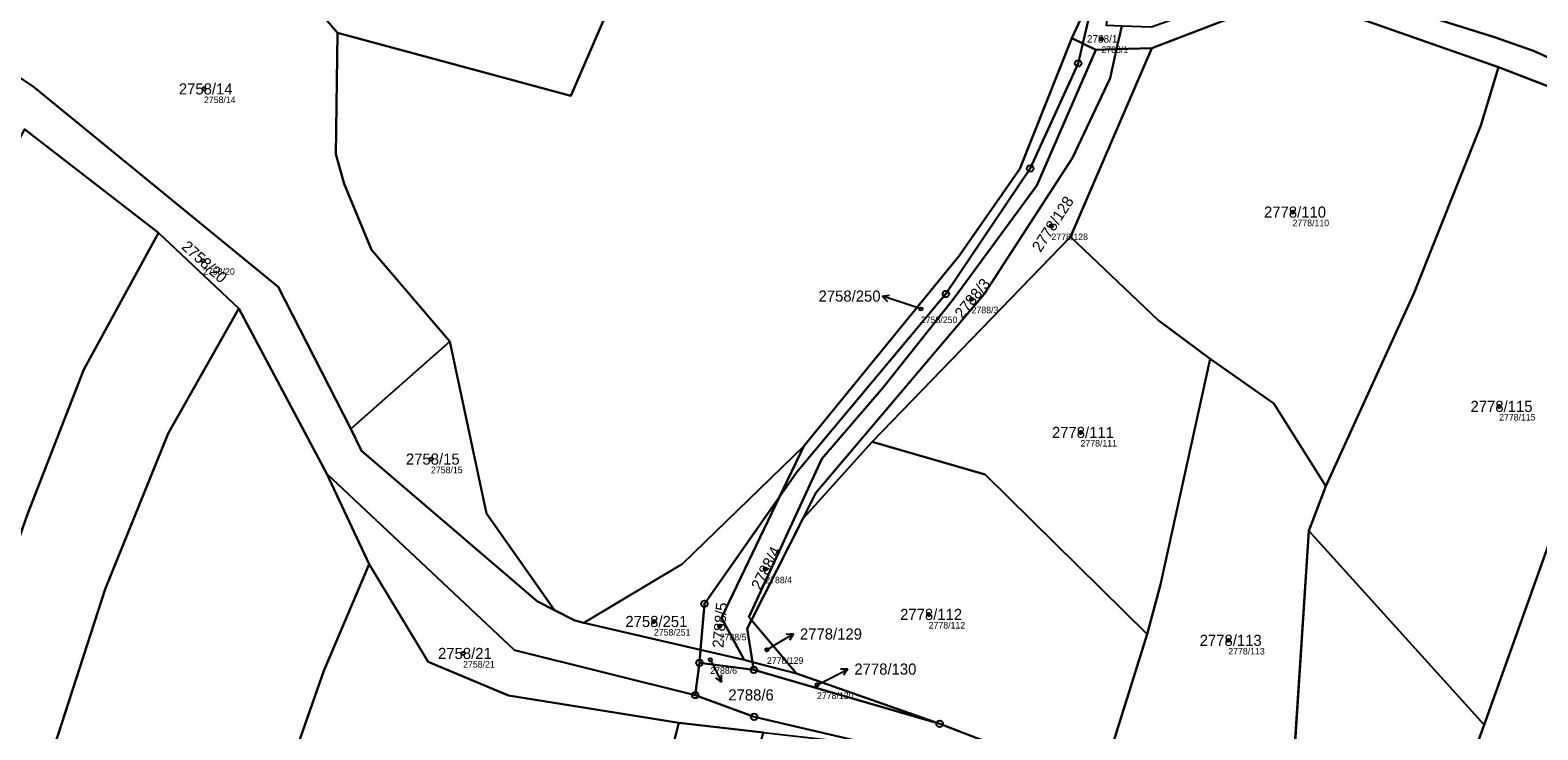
# Model space of a CAD drawing. Extents: x -739214 to -733252, y -1147612 to -1142842.
# Drawn here: x -738174 to -737943.5, y -1144167.5 to -1144060.6 of the extents above; entities that cross this region are included whole.
import ezdxf

# ---------------------------------------------------------------- set-up
doc = ezdxf.new("R2010")
doc.units = 0
for name, color, linetype in [('Definiční body', 7, 'Continuous'), ('Hranice parcel', 7, 'Continuous'), ('Parcelní čísla', 7, 'Continuous'), ('Polygon parcely', 7, 'Continuous'), ('Pop  PČ popisy', 7, 'Continuous'), ('Značky bodu BP', 7, 'Continuous')]:
    doc.layers.add(name, color=color, linetype=linetype)

msp = doc.modelspace()

# ---------------------------------------------------------------- linework, layer by layer
at = {"layer": 'Definiční body'}
for centre in [(-738010.25, -1144061.91), (-738147.45, -1144069.56), (-737981.03, -1144088.39), (-738017.89, -1144090.51), (-738147.58, -1144095.81), (-738037.85, -1144103.2), (-738030.1, -1144101.7), (-737949.46, -1144118.09), (-738013.45, -1144122.07), (-738112.74, -1144126.15), (-738061.64, -1144142.97), (-738078.66, -1144150.97), (-738068.61, -1144151.7), (-738036.66, -1144149.89), (-737990.86, -1144153.86), (-738107.83, -1144155.86), (-738061.39, -1144155.29), (-738070.05, -1144156.82), (-738053.73, -1144160.66)]:
    msp.add_circle(centre, 0.25, dxfattribs=at)
at = {"layer": 'Hranice parcel'}
for p, q in [((-738013.1, -1144062.62), (-738009.89, -1144048.95)), ((-738007.14, -1144059.96), (-738007.93, -1144063.48)), ((-738002.53, -1144063.31), (-738014.98, -1144092.16)), ((-738014.77, -1144061.81), (-738013.1, -1144062.62)), ((-738013.1, -1144062.62), (-738011.1, -1144063.58)), ((-738011.1, -1144063.58), (-738007.93, -1144063.48)), ((-738007.93, -1144063.48), (-738002.53, -1144063.31)), ((-737919.88, -1144077.7), (-737949.57, -1144066.24)), ((-738174.89, -1144075.7), (-738154.42, -1144091.58)), ((-737951.75, -1144166.77), (-737919.88, -1144077.7)), ((-738154.42, -1144091.58), (-738142.14, -1144103.13)), ((-738014.98, -1144092.16), (-738045.31, -1144123.51)), ((-738142.14, -1144103.13), (-738128.69, -1144128.42)), ((-738125, -1144121.52), (-738109.86, -1144108.18)), ((-738045.31, -1144123.51), (-738055.92, -1144135.29)), ((-738055.76, -1144124.16), (-738059.47, -1144131.9)), ((-738128.69, -1144128.42), (-738122.19, -1144142.23)), ((-737978.57, -1144137.13), (-737975.97, -1144130.27)), ((-738055.92, -1144135.29), (-738063.75, -1144150.77)), ((-737981.88, -1144188.4), (-737978.57, -1144137.13)), ((-737951.75, -1144166.77), (-737978.57, -1144137.13)), ((-738071.52, -1144155.32), (-738089.39, -1144151.16)), ((-738063.75, -1144150.77), (-738056.85, -1144158.93)), ((-738010.51, -1144176.06), (-738003.24, -1144152.93)), ((-738071.68, -1144157.31), (-738071.52, -1144155.32)), ((-738071.52, -1144155.32), (-738064.89, -1144156.86)), ((-738071.68, -1144157.31), (-738072.34, -1144162.22)), ((-738063.38, -1144158.37), (-738071.68, -1144157.31)), ((-738064.89, -1144156.86), (-738063.57, -1144157.2)), ((-738063.57, -1144157.2), (-738056.85, -1144158.93)), ((-738063.57, -1144157.2), (-738063.38, -1144158.37)), ((-738034.98, -1144166.63), (-738063.38, -1144158.37)), ((-738056.85, -1144158.93), (-738034.98, -1144166.63)), ((-738084.93, -1144206.16), (-738074.87, -1144166.48)), ((-738074.87, -1144166.48), (-738061.91, -1144167.95)), ((-738010.51, -1144176.06), (-738034.98, -1144166.63)), ((-737962.59, -1144196.71), (-737951.75, -1144166.77))]:
    msp.add_line(p, q, dxfattribs=at)
for points in [[(-738127.05, -1144061.01), (-738091.39, -1144070.6), (-738073.95, -1144030.31), (-738086.33, -1144026.73), (-738094.88, -1144023.42), (-738135.77, -1144012.95), (-738153.39, -1144042.78)], [(-738014.77, -1144061.81), (-738012.25, -1144056.3), (-738010.6, -1144023.28)], [(-738153.39, -1144042.78), (-738138.19, -1144047.98), (-738127.05, -1144061.01)], [(-737949.57, -1144066.24), (-737975.58, -1144057.09), (-737982.96, -1144055.8), (-738002.53, -1144063.31)], [(-737967.49, -1144056.26), (-737950.32, -1144061.58), (-737944.21, -1144063.75), (-737932.49, -1144068.97), (-737914.29, -1144076.59)], [(-738127.05, -1144061.01), (-738127.31, -1144079.52), (-738126.02, -1144084.05), (-738121.83, -1144094.15), (-738109.86, -1144108.18)], [(-738184.48, -1144061.95), (-738173.58, -1144069.2), (-738136.12, -1144099.8), (-738125, -1144121.52)], [(-738011.1, -1144063.58), (-738020.13, -1144084.3), (-738032.83, -1144101.61), (-738043.64, -1144115.21), (-738053.01, -1144126.13), (-738064.14, -1144150.32), (-738063.75, -1144150.77)], [(-738059.47, -1144131.9), (-738056.87, -1144128.19), (-738034.02, -1144100.91), (-738021.15, -1144081.71), (-738013.81, -1144065.65), (-738013.1, -1144062.62)], [(-738007.93, -1144063.48), (-738008.92, -1144067.91), (-738014.68, -1144080.07), (-738028.2, -1144100.93), (-738053.92, -1144131.33), (-738055.92, -1144135.29)], [(-738055.76, -1144124.16), (-738032.02, -1144095.1), (-738022.71, -1144081.77), (-738014.77, -1144061.81)], [(-737975.97, -1144130.27), (-737962.5, -1144100.82), (-737952.27, -1144075.17), (-737949.57, -1144066.24)], [(-738198.48, -1144212.6), (-738186.89, -1144170.23), (-738174.45, -1144134.55), (-738165.8, -1144112.47), (-738154.42, -1144091.58)], [(-738014.98, -1144092.16), (-738001.58, -1144104.9), (-737993.61, -1144110.81)], [(-738205.64, -1144348.69), (-738193.32, -1144271.69), (-738179.35, -1144203.89), (-738173.61, -1144180.21), (-738162.54, -1144146.03), (-738152.91, -1144122.22), (-738142.14, -1144103.13)], [(-738109.86, -1144108.18), (-738104.24, -1144134.49), (-738093.87, -1144149.24)], [(-738003.24, -1144152.93), (-738001.24, -1144145.32), (-737993.61, -1144110.81)], [(-737993.61, -1144110.81), (-737983.92, -1144117.66), (-737975.97, -1144130.27)], [(-738125, -1144121.52), (-738123.39, -1144124.91), (-738096.45, -1144147.92), (-738093.87, -1144149.24)], [(-738045.31, -1144123.51), (-738028.05, -1144128.49), (-738003.24, -1144152.93)], [(-738089.39, -1144151.16), (-738074.3, -1144142.14), (-738055.76, -1144124.16)], [(-738128.69, -1144128.42), (-738099.97, -1144155.35), (-738072.34, -1144162.22)], [(-738071.52, -1144155.32), (-738070.95, -1144148.27), (-738059.47, -1144131.9)], [(-738059.47, -1144131.9), (-738068.34, -1144150.4), (-738064.89, -1144156.86)], [(-738144.12, -1144205.48), (-738136.5, -1144179.63), (-738129.14, -1144158.51), (-738122.19, -1144142.23)], [(-738122.19, -1144142.23), (-738113.17, -1144157.14), (-738100.87, -1144162.28), (-738074.87, -1144166.48)], [(-738093.87, -1144149.24), (-738090.75, -1144150.84), (-738089.39, -1144151.16)], [(-738063.75, -1144150.77), (-738064.4, -1144152.05), (-738063.57, -1144157.2)], [(-738072.34, -1144162.22), (-738063.34, -1144165.55), (-738044.81, -1144169.88)]]:
    msp.add_lwpolyline(points, dxfattribs=at)
at = {"layer": 'Polygon parcely'}
for points in [[(-738138.19, -1144047.98), (-738127.05, -1144061.01), (-738091.39, -1144070.6), (-738073.95, -1144030.31), (-738086.33, -1144026.73), (-738094.88, -1144023.42), (-738135.77, -1144012.95), (-738153.39, -1144042.78)], [(-738009.89, -1144048.95), (-738010.6, -1144023.28), (-738012.25, -1144056.3), (-738014.77, -1144061.81), (-738013.1, -1144062.62)], [(-738173.58, -1144069.2), (-738136.12, -1144099.8), (-738125, -1144121.52), (-738109.86, -1144108.18), (-738121.83, -1144094.15), (-738126.02, -1144084.05), (-738127.31, -1144079.52), (-738127.05, -1144061.01), (-738138.19, -1144047.98), (-738153.39, -1144042.78), (-738182.49, -1144037.88), (-738184.48, -1144061.95)], [(-737950.32, -1144061.58), (-737944.21, -1144063.75), (-737932.49, -1144068.97), (-737914.29, -1144076.59), (-737913.71, -1144055.05), (-737923.72, -1144055.39), (-737929.32, -1144055.23), (-737934.66, -1144053.55), (-737964.98, -1144037.92), (-737967.49, -1144056.26)], [(-738007.14, -1144059.96), (-738009.49, -1144059.87), (-738008.56, -1144050.53), (-738009.89, -1144048.95), (-738013.1, -1144062.62), (-738011.1, -1144063.58), (-738007.93, -1144063.48)], [(-737982.96, -1144055.8), (-738002.53, -1144063.31), (-738014.98, -1144092.16), (-738001.58, -1144104.9), (-737993.61, -1144110.81), (-737983.92, -1144117.66), (-737975.97, -1144130.27), (-737962.5, -1144100.82), (-737952.27, -1144075.17), (-737949.57, -1144066.24), (-737975.58, -1144057.09)], [(-738064.89, -1144156.86), (-738063.57, -1144157.2), (-738064.4, -1144152.05), (-738063.75, -1144150.77), (-738064.14, -1144150.32), (-738053.01, -1144126.13), (-738043.64, -1144115.21), (-738032.83, -1144101.61), (-738020.13, -1144084.3), (-738011.1, -1144063.58), (-738013.1, -1144062.62), (-738013.81, -1144065.65), (-738021.15, -1144081.71), (-738034.02, -1144100.91), (-738056.87, -1144128.19), (-738059.47, -1144131.9), (-738068.34, -1144150.4)], [(-738011.1, -1144063.58), (-738020.13, -1144084.3), (-738032.83, -1144101.61), (-738043.64, -1144115.21), (-738053.01, -1144126.13), (-738064.14, -1144150.32), (-738063.75, -1144150.77), (-738055.92, -1144135.29), (-738053.92, -1144131.33), (-738028.2, -1144100.93), (-738014.68, -1144080.07), (-738008.92, -1144067.91), (-738007.93, -1144063.48)], [(-738013.1, -1144062.62), (-738014.77, -1144061.81), (-738022.71, -1144081.77), (-738032.02, -1144095.1), (-738055.76, -1144124.16), (-738059.47, -1144131.9), (-738056.87, -1144128.19), (-738034.02, -1144100.91), (-738021.15, -1144081.71), (-738013.81, -1144065.65)], [(-738028.2, -1144100.93), (-738053.92, -1144131.33), (-738055.92, -1144135.29), (-738045.31, -1144123.51), (-738014.98, -1144092.16), (-738002.53, -1144063.31), (-738007.93, -1144063.48), (-738008.92, -1144067.91), (-738014.68, -1144080.07)], [(-737919.88, -1144077.7), (-737949.57, -1144066.24), (-737952.27, -1144075.17), (-737962.5, -1144100.82), (-737975.97, -1144130.27), (-737978.57, -1144137.13), (-737951.75, -1144166.77)], [(-738165.8, -1144112.47), (-738154.42, -1144091.58), (-738174.89, -1144075.7), (-738185.18, -1144094.82), (-738193.2, -1144112.69), (-738202.51, -1144136.07), (-738208.35, -1144153.81), (-738215.38, -1144178.91), (-738223.83, -1144215.74), (-738198.48, -1144212.6), (-738186.89, -1144170.23), (-738174.45, -1144134.55)], [(-737891.15, -1144088.14), (-737919.88, -1144077.7), (-737951.75, -1144166.77), (-737962.59, -1144196.71), (-737961.08, -1144197.36), (-737938.85, -1144203.13), (-737921.64, -1144210.16), (-737908.2, -1144216.58), (-737882.19, -1144138.84), (-737868.79, -1144090.89)], [(-738179.35, -1144203.89), (-738173.61, -1144180.21), (-738162.54, -1144146.03), (-738152.91, -1144122.22), (-738142.14, -1144103.13), (-738154.42, -1144091.58), (-738165.8, -1144112.47), (-738174.45, -1144134.55), (-738186.89, -1144170.23), (-738198.48, -1144212.6), (-738203.26, -1144250.7), (-738221.27, -1144346.76), (-738205.64, -1144348.69), (-738193.32, -1144271.69)], [(-738045.31, -1144123.51), (-738028.05, -1144128.49), (-738003.24, -1144152.93), (-738001.24, -1144145.32), (-737993.61, -1144110.81), (-738001.58, -1144104.9), (-738014.98, -1144092.16)], [(-738172.43, -1144352.14), (-738151.89, -1144235.51), (-738145.42, -1144209.6), (-738144.12, -1144205.48), (-738136.5, -1144179.63), (-738129.14, -1144158.51), (-738122.19, -1144142.23), (-738128.69, -1144128.42), (-738142.14, -1144103.13), (-738152.91, -1144122.22), (-738162.54, -1144146.03), (-738173.61, -1144180.21), (-738179.35, -1144203.89), (-738193.32, -1144271.69), (-738205.64, -1144348.69)], [(-738123.39, -1144124.91), (-738096.45, -1144147.92), (-738093.87, -1144149.24), (-738104.24, -1144134.49), (-738109.86, -1144108.18), (-738125, -1144121.52)], [(-737978.57, -1144137.13), (-737975.97, -1144130.27), (-737983.92, -1144117.66), (-737993.61, -1144110.81), (-738001.24, -1144145.32), (-738003.24, -1144152.93), (-738010.51, -1144176.06), (-737981.88, -1144188.4)], [(-738056.85, -1144158.93), (-738034.98, -1144166.63), (-738010.51, -1144176.06), (-738003.24, -1144152.93), (-738028.05, -1144128.49), (-738045.31, -1144123.51), (-738055.92, -1144135.29), (-738063.75, -1144150.77)], [(-738071.52, -1144155.32), (-738070.95, -1144148.27), (-738059.47, -1144131.9), (-738055.76, -1144124.16), (-738074.3, -1144142.14), (-738089.39, -1144151.16)], [(-738044.81, -1144169.88), (-738063.34, -1144165.55), (-738072.34, -1144162.22), (-738099.97, -1144155.35), (-738128.69, -1144128.42), (-738122.19, -1144142.23), (-738113.17, -1144157.14), (-738100.87, -1144162.28), (-738074.87, -1144166.48), (-738061.91, -1144167.95)], [(-738064.89, -1144156.86), (-738068.34, -1144150.4), (-738059.47, -1144131.9), (-738070.95, -1144148.27), (-738071.52, -1144155.32)], [(-737951.75, -1144166.77), (-737978.57, -1144137.13), (-737981.88, -1144188.4), (-737962.59, -1144196.71)], [(-738084.93, -1144206.16), (-738074.87, -1144166.48), (-738100.87, -1144162.28), (-738113.17, -1144157.14), (-738122.19, -1144142.23), (-738129.14, -1144158.51), (-738136.5, -1144179.63), (-738144.12, -1144205.48), (-738096.86, -1144217.4), (-738093.42, -1144206.83)], [(-738056.85, -1144158.93), (-738063.75, -1144150.77), (-738064.4, -1144152.05), (-738063.57, -1144157.2)], [(-738071.68, -1144157.31), (-738063.38, -1144158.37), (-738063.57, -1144157.2), (-738064.89, -1144156.86), (-738071.52, -1144155.32)], [(-738063.38, -1144158.37), (-738034.98, -1144166.63), (-738056.85, -1144158.93), (-738063.57, -1144157.2)], [(-738072.86, -1144205.49), (-738061.91, -1144167.95), (-738074.87, -1144166.48), (-738084.93, -1144206.16)]]:
    msp.add_lwpolyline(points, close=True, dxfattribs=at)
for points in [[(-738073.95, -1144030.31), (-738091.39, -1144070.6), (-738127.05, -1144061.01), (-738127.31, -1144079.52), (-738126.02, -1144084.05), (-738121.83, -1144094.15), (-738109.86, -1144108.18), (-738104.24, -1144134.49), (-738093.87, -1144149.24), (-738090.75, -1144150.84), (-738089.39, -1144151.16), (-738074.3, -1144142.14), (-738055.76, -1144124.16), (-738032.02, -1144095.1), (-738022.71, -1144081.77), (-738014.77, -1144061.81), (-738012.25, -1144056.3)], [(-737932.49, -1144068.97), (-737944.21, -1144063.75), (-737950.32, -1144061.58), (-737967.49, -1144056.26), (-737974.8, -1144054.22), (-737982.5, -1144052.91), (-738002.61, -1144060.14), (-738007.14, -1144059.96), (-738007.93, -1144063.48), (-738002.53, -1144063.31), (-737982.96, -1144055.8), (-737975.58, -1144057.09), (-737949.57, -1144066.24), (-737919.88, -1144077.7)], [(-738174.89, -1144075.7), (-738154.42, -1144091.58), (-738142.14, -1144103.13), (-738128.69, -1144128.42), (-738099.97, -1144155.35), (-738072.34, -1144162.22), (-738071.68, -1144157.31), (-738071.52, -1144155.32), (-738089.39, -1144151.16), (-738090.75, -1144150.84), (-738093.87, -1144149.24), (-738096.45, -1144147.92), (-738123.39, -1144124.91), (-738125, -1144121.52), (-738136.12, -1144099.8), (-738173.58, -1144069.2), (-738184.48, -1144061.95)], [(-737938.85, -1144203.13), (-737961.08, -1144197.36), (-737962.59, -1144196.71), (-737981.88, -1144188.4), (-738010.51, -1144176.06), (-738034.98, -1144166.63), (-738063.38, -1144158.37), (-738071.68, -1144157.31), (-738072.34, -1144162.22), (-738063.34, -1144165.55), (-738044.81, -1144169.88), (-738037.16, -1144171.67), (-738013.27, -1144181.12), (-738011.75, -1144181.72), (-737997.19, -1144187.96), (-737983.22, -1144193.94), (-737982.94, -1144194.06), (-737972.54, -1144198.24), (-737971.4, -1144198.56), (-737960.13, -1144201.71), (-737940.37, -1144207.23)]]:
    msp.add_lwpolyline(points, dxfattribs=at)
at = {"layer": 'Pop  PČ popisy'}
for p, q in [((-738043.76, -1144101.25), (-738042.66, -1144101.09)), ((-738040.91, -1144102.18), (-738043.76, -1144101.25)), ((-738043.76, -1144101.25), (-738042.97, -1144102.04)), ((-738037.85, -1144103.2), (-738040.91, -1144102.18)), ((-738059.92, -1144154.41), (-738057.35, -1144152.86)), ((-738057.35, -1144152.86), (-738058.46, -1144152.95)), ((-738057.35, -1144152.86), (-738057.95, -1144153.81)), ((-738061.39, -1144155.29), (-738059.92, -1144154.41)), ((-738070.05, -1144156.82), (-738069.67, -1144157.56)), ((-738069.67, -1144157.56), (-738068.31, -1144160.23)), ((-738051.69, -1144159.62), (-738049.02, -1144158.26)), ((-738049.02, -1144158.26), (-738050.14, -1144158.27)), ((-738049.02, -1144158.26), (-738049.68, -1144159.16)), ((-738068.31, -1144160.23), (-738069.21, -1144159.57)), ((-738068.31, -1144160.23), (-738068.32, -1144159.11)), ((-738053.73, -1144160.66), (-738051.69, -1144159.62))]:
    msp.add_line(p, q, dxfattribs=at)
at = {"layer": 'Značky bodu BP'}
for centre, radius in [((-738013.81, -1144065.65), 0.5), ((-738013.81, -1144065.65), 0.0303), ((-738021.15, -1144081.71), 0.5), ((-738021.15, -1144081.71), 0.0303), ((-738034.02, -1144100.91), 0.5), ((-738034.02, -1144100.91), 0.0303), ((-738070.95, -1144148.27), 0.5), ((-738070.95, -1144148.27), 0.0303), ((-738071.68, -1144157.31), 0.5), ((-738071.68, -1144157.31), 0.0303), ((-738063.38, -1144158.37), 0.5), ((-738063.38, -1144158.37), 0.0303), ((-738072.34, -1144162.22), 0.5), ((-738072.34, -1144162.22), 0.0303), ((-738063.34, -1144165.55), 0.5), ((-738063.34, -1144165.55), 0.0303), ((-738034.98, -1144166.63), 0.5), ((-738034.98, -1144166.63), 0.0303)]:
    msp.add_circle(centre, radius, dxfattribs=at)

# ---------------------------------------------------------------- texts
at = {"layer": 'Definiční body'}
for s, p in [('2788/1', (-738010.25, -1144064.07)), ('2758/14', (-738147.45, -1144071.72)), ('2778/128', (-738017.89, -1144092.67)), ('2778/110', (-737981.03, -1144090.55)), ('2758/20', (-738147.58, -1144097.97)), ('2788/3', (-738030.1, -1144103.86)), ('2758/250', (-738037.85, -1144105.36)), ('2778/115', (-737949.46, -1144120.25)), ('2778/111', (-738013.45, -1144124.23)), ('2758/15', (-738112.74, -1144128.31)), ('2788/4', (-738061.64, -1144145.13)), ('2778/112', (-738036.66, -1144152.05)), ('2758/251', (-738078.66, -1144153.13)), ('2788/5', (-738068.61, -1144153.86)), ('2778/113', (-737990.86, -1144156.02)), ('2758/21', (-738107.83, -1144158.02)), ('2788/6', (-738070.05, -1144158.98)), ('2778/129', (-738061.39, -1144157.45)), ('2778/130', (-738053.73, -1144162.82))]:
    msp.add_text(s, height=1, dxfattribs=at).set_placement(p)
at = {"layer": 'Parcelní čísla'}
for s, height, p in [('2788/1', 1.14, (-738012.47, -1144062.48)), ('2758/14', 1.7, (-738151.29, -1144070.41)), ('2778/110', 1.7, (-737985.4, -1144089.24)), ('2758/250', 1.7, (-738053.5, -1144102.08)), ('2778/115', 1.7, (-737953.83, -1144118.94)), ('2778/111', 1.7, (-738017.82, -1144122.92)), ('2758/15', 1.7, (-738116.58, -1144127)), ('2778/112', 1.7, (-738041.03, -1144150.74)), ('2758/251', 1.7, (-738083.03, -1144151.82)), ('2778/129', 1.7, (-738056.34, -1144153.73)), ('2778/113', 1.7, (-737995.23, -1144154.71)), ('2758/21', 1.7, (-738111.67, -1144156.71)), ('2778/130', 1.7, (-738048.02, -1144159.1)), ('2788/6', 1.7, (-738067.29, -1144163.05))]:
    msp.add_text(s, height=height, dxfattribs=at).set_placement(p)
for s, rotation, p in [('2778/128', 57, (-738019.56, -1144094.64)), ('2758/20', 318, (-738151, -1144093.87)), ('2788/3', 51, (-738031.52, -1144104.8)), ('2788/4', 63, (-738062.38, -1144146.3)), ('2788/5', 85, (-738068.05, -1144155.07))]:
    msp.add_text(s, height=1.7, rotation=rotation, dxfattribs=at).set_placement(p)

doc.saveas('drawing.dxf')
